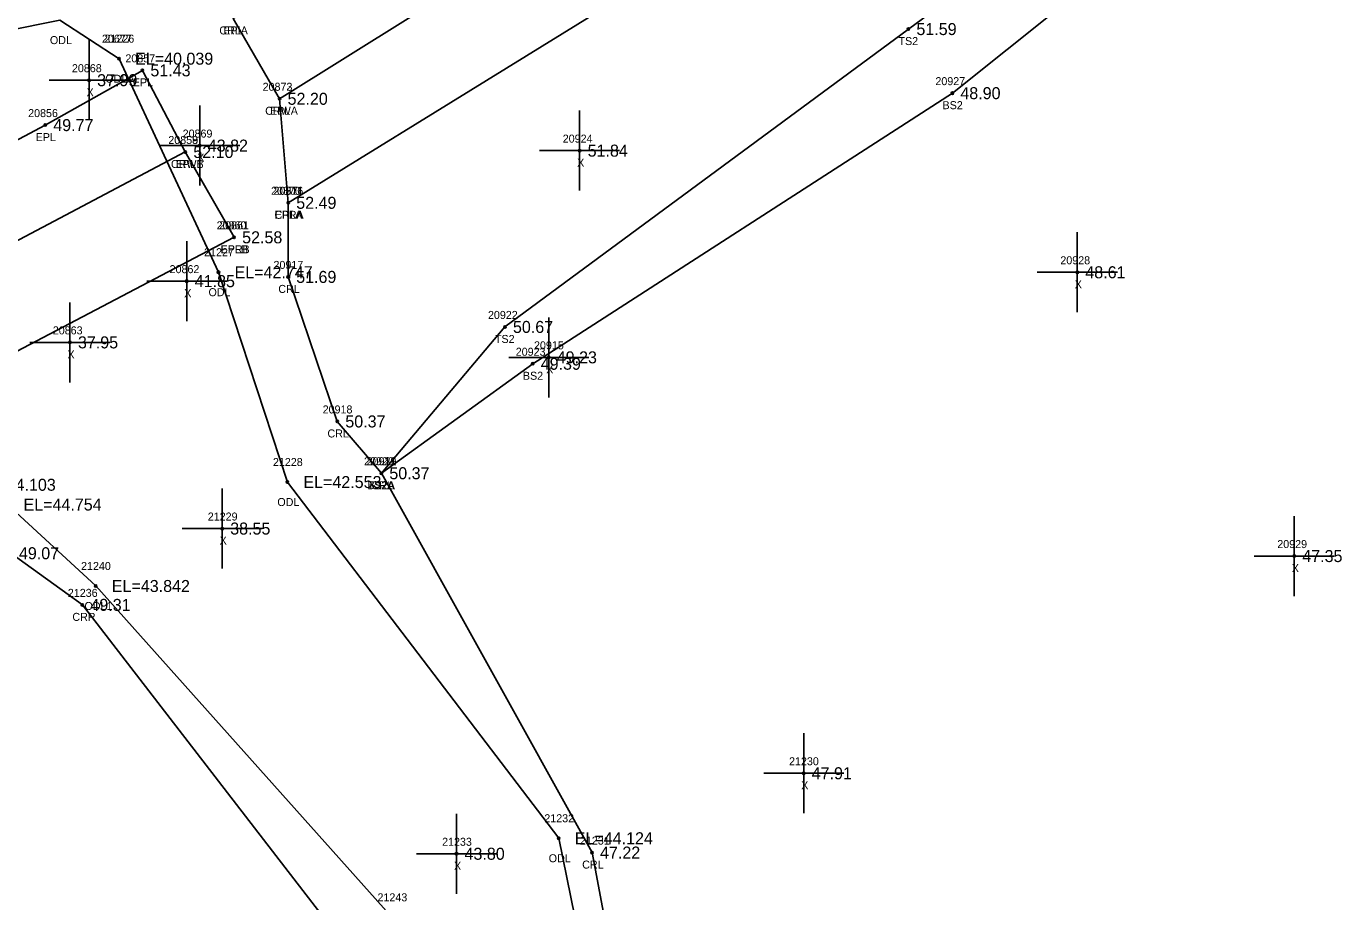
# Model space of a CAD drawing. Extents: x 2420351 to 2422725, y 845330 to 846558.
# Drawn here: x 2421778.1 to 2421942.5, y 845732.5 to 845841.9 of the extents above; entities that cross this region are included whole.
import ezdxf

# ---------------------------------------------------------------- set-up
doc = ezdxf.new("R2010")
doc.units = 0
for name, color, linetype in [('BR_GRID DOTS', 7, 'Continuous'), ('RD_DTM_BkLn1', 7, 'Continuous'), ('RD_DTM_BkLn2', 7, 'Continuous'), ('RD_DTM_BkLn_txCode', 7, 'Continuous'), ('RD_EX_H2O', 7, 'Continuous'), ('RD_EX_H2O_txCode', 7, 'Continuous'), ('RD_EX_Misc', 7, 'Continuous'), ('RD_EX_Misc_txCode', 7, 'Continuous'), ('RD_EX_Road', 7, 'Continuous'), ('RD_EX_Road_txCode', 7, 'Continuous'), ('RD_EX_TX_H2O_ELEV', 7, 'Continuous'), ('RD_EX_TX_Misc_ELEV', 7, 'Continuous'), ('RD_EX_TX_Road_ELEV', 7, 'Continuous'), ('RD_HC_Survey_ELEV', 7, 'Continuous'), ('RD_HC_Survey_txCode', 7, 'Continuous'), ('RD_SMD_Locator', 7, 'Continuous')]:
    doc.layers.add(name, color=color, linetype=linetype)

msp = doc.modelspace()

# ---------------------------------------------------------------- linework, layer by layer
at = {"layer": 'BR_GRID DOTS'}
for p, q in [((2421759.07, 845805.68), (2421797.91, 845826.17)), ((2421764.83, 845794.95), (2421804.01, 845815.51))]:
    msp.add_line(p, q, dxfattribs=at)
msp.add_lwpolyline([(2421764.83, 845794.95), (2421759.07, 845805.68), (2421753.59, 845815.63), (2421766.83, 845822.3), (2421780.42, 845829.53), (2421792.55, 845836.37), (2421797.91, 845826.17), (2421804.01, 845815.51)], dxfattribs=at)
for centre in [(2421792.55, 845836.37), (2421780.42, 845829.53), (2421797.91, 845826.17), (2421797.91, 845826.17), (2421804.01, 845815.51)]:
    msp.add_circle(centre, 0.15, dxfattribs=at)
at = {"layer": 'RD_DTM_BkLn1'}
msp.add_lwpolyline([(2421809.69, 845832.82), (2421858.88, 845863.61), (2421946.63, 845925.83), (2421988.11, 845958.04), (2422060.85, 846015.47), (2422145.87, 846082.37), (2422217.73, 846139.26), (2422291.07, 846197.06), (2422441.76, 846315.63), (2422509.48, 846369.12), (2422585.38, 846428.46), (2422650.19, 846479.15)], dxfattribs=at)
at = {"layer": 'RD_DTM_BkLn2'}
for points in [[(2421822.4, 845786.03), (2421837.84, 845804.31), (2421888.24, 845841.53), (2421930.25, 845872.55), (2421966.04, 845899.72), (2422004.21, 845932.1), (2422041.57, 845964.03)], [(2421822.4, 845786.03), (2421841.31, 845799.71), (2421893.73, 845833.52), (2421934.91, 845866.48), (2422007.56, 845925.47), (2422041.57, 845964.03)]]:
    msp.add_lwpolyline(points, dxfattribs=at)
at = {"layer": 'RD_EX_H2O'}
for points in [[(2421789.64, 845837.83), (2421782.25, 845842.65), (2421762.14, 845838.6), (2421745.54, 845847.69), (2421715.82, 845873.29), (2421690.16, 845897.6), (2421662.52, 845937.52), (2421691.81, 845952.74), (2421695.52, 845998.98), (2421690.3, 846033.46), (2421790.46, 846058.61), (2421873.55, 846071.45), (2421916.6, 846080.01)], [(2421789.64, 845837.83), (2421802.06, 845811.15), (2421810.66, 845784.93), (2421844.56, 845740.42), (2421856.1, 845683.72), (2421854.89, 845664.88), (2421843.25, 845658.16), (2421829.21, 845628.83), (2421830.77, 845610.33), (2421843.38, 845580.1), (2421828.19, 845558.94), (2421831.91, 845499.14), (2421809.98, 845486.71), (2421808.79, 845466.96), (2421839.47, 845434.68), (2421874.6, 845421.86), (2421897.47, 845382.52), (2421913.19, 845366.87)], [(2421810.77, 845819.82), (2421810.76, 845810.56), (2421816.9, 845792.5), (2421822.4, 845786.03), (2421848.72, 845738.63), (2421858.75, 845685.13), (2421860.35, 845662.88), (2421845.9, 845650.47), (2421833.11, 845629.75), (2421840.79, 845614.06), (2421848.44, 845579.41), (2421832.04, 845554.52), (2421837.19, 845498.45), (2421811.62, 845484.13), (2421811.72, 845469.11), (2421841.99, 845438.03), (2421875.97, 845424.56), (2421900.41, 845383.13), (2421915.29, 845367.51)], [(2421769.97, 845784.59), (2421775.7, 845782.12), (2421786.73, 845771.94), (2421823.71, 845730.54), (2421836.28, 845679.34), (2421832.24, 845660.92), (2421820.77, 845638.45), (2421823.1, 845608.96), (2421831.71, 845583.35), (2421823.31, 845575.86), (2421811.92, 845548.94), (2421818.99, 845509.7), (2421790.81, 845485.52), (2421791.34, 845474.13), (2421803.96, 845452.08), (2421836.18, 845421.02), (2421870.76, 845406.66), (2421878.5, 845385.15), (2421867.47, 845378.72), (2421847.36, 845376.11), (2421845.3, 845344.22)], [(2421768.08, 845778.29), (2421776.13, 845776.03), (2421785.06, 845769.58), (2421818.61, 845726.06), (2421831.42, 845677.9), (2421825.05, 845663.86), (2421816.1, 845638.14), (2421820.64, 845608.52), (2421828.09, 845585.14), (2421817.9, 845575.21), (2421808.75, 845549.61), (2421816.7, 845511.81), (2421785.75, 845489.97), (2421789.04, 845473.23), (2421801.09, 845449.66), (2421834.75, 845418.44), (2421870.95, 845402.12), (2421876.24, 845387.07), (2421866.97, 845385.32), (2421844.91, 845376.57), (2421842.84, 845344.63)]]:
    msp.add_lwpolyline(points, dxfattribs=at)
at = {"layer": 'RD_EX_Misc'}
for p, q in [((2421785.9, 845830.14), (2421785.9, 845840.14)), ((2421780.9, 845835.14), (2421790.9, 845835.14)), ((2421799.72, 845821.97), (2421799.72, 845831.97)), ((2421847.17, 845821.34), (2421847.17, 845831.34)), ((2421794.72, 845826.97), (2421804.72, 845826.97)), ((2421842.17, 845826.34), (2421852.17, 845826.34)), ((2421909.34, 845806.14), (2421909.34, 845816.14)), ((2421798.09, 845805.03), (2421798.09, 845815.03)), ((2421904.34, 845811.14), (2421914.34, 845811.14)), ((2421793.09, 845810.03), (2421803.09, 845810.03)), ((2421783.5, 845797.38), (2421783.5, 845807.38)), ((2421843.31, 845795.51), (2421843.31, 845805.51)), ((2421778.5, 845802.38), (2421788.5, 845802.38)), ((2421838.31, 845800.51), (2421848.31, 845800.51)), ((2421802.52, 845774.12), (2421802.52, 845784.12)), ((2421936.44, 845770.68), (2421936.44, 845780.68)), ((2421797.52, 845779.12), (2421807.52, 845779.12)), ((2421931.44, 845775.68), (2421941.44, 845775.68)), ((2421875.16, 845743.54), (2421875.16, 845753.54)), ((2421870.16, 845748.54), (2421880.16, 845748.54)), ((2421831.79, 845733.48), (2421831.79, 845743.48)), ((2421826.79, 845738.48), (2421836.79, 845738.48))]:
    msp.add_line(p, q, dxfattribs=at)
at = {"layer": 'RD_EX_Road'}
for points in [[(2421810.77, 845819.82), (2421809.69, 845832.82), (2421803.88, 845842.86), (2421852.96, 845873.69), (2421939.48, 845935.12), (2421980.78, 845967.01), (2422140.12, 846092.81), (2422210.03, 846148.43), (2422282.88, 846205.21), (2422291.79, 846212.09), (2422354.49, 846261.98), (2422400.82, 846297.88), (2422417.34, 846311.65), (2422435.4, 846324.77), (2422462.49, 846346.77), (2422472.85, 846354.85), (2422502.3, 846378.16), (2422578.05, 846437.54), (2422605.64, 846459.09), (2422626.64, 846476.17), (2422642.61, 846488.86)], [(2421810.77, 845819.82), (2421865.31, 845853.52), (2421953.26, 845916.07), (2421995.06, 845948.03), (2422068.36, 846005.98), (2422153.46, 846073.36), (2422229.55, 846134.03), (2422245.4, 846145.63), (2422297.08, 846186.88), (2422369.77, 846243.69), (2422382.04, 846253.08), (2422449.02, 846305.97), (2422517.14, 846360.1), (2422592.58, 846419.1), (2422657.51, 846470.1)]]:
    msp.add_lwpolyline(points, dxfattribs=at)
at = {"layer": 'RD_SMD_Locator'}
for centre in [(2421888.24, 845841.53), (2421789.64, 845837.83), (2421789.64, 845837.83), (2421785.9, 845835.14), (2421893.73, 845833.52), (2421809.69, 845832.82), (2421809.69, 845832.82), (2421799.72, 845826.97), (2421847.17, 845826.34), (2421810.77, 845819.82), (2421810.77, 845819.82), (2421810.77, 845819.82), (2421804.01, 845815.51), (2421802.06, 845811.15), (2421810.76, 845810.56), (2421909.34, 845811.14), (2421798.09, 845810.03), (2421837.84, 845804.31), (2421783.5, 845802.38), (2421841.31, 845799.71), (2421843.31, 845800.51), (2421816.9, 845792.5), (2421822.4, 845786.03), (2421822.4, 845786.03), (2421822.4, 845786.03), (2421810.66, 845784.93), (2421802.52, 845779.12), (2421936.44, 845775.68), (2421786.73, 845771.94), (2421785.06, 845769.58), (2421875.16, 845748.54), (2421844.56, 845740.42), (2421831.79, 845738.48), (2421848.72, 845738.63)]:
    msp.add_circle(centre, 0.15, dxfattribs=at)

# ---------------------------------------------------------------- texts
at = {"layer": 'RD_DTM_BkLn_txCode'}
for s, p in [('TS2', (2421887, 845839.53)), ('20927', (2421891.61, 845834.52)), ('BS2', (2421892.5, 845831.52)), ('20922', (2421835.72, 845805.31)), ('TS2', (2421836.59, 845802.31)), ('20923', (2421839.19, 845800.71)), ('BS2', (2421840.08, 845797.71)), ('20920', (2421820.24, 845787.03)), ('20921', (2421820.56, 845787.03)), ('TS2A', (2421820.67, 845784.03)), ('BS2A', (2421820.68, 845784.03))]:
    msp.add_text(s, height=1, dxfattribs=at).set_placement(p)
at = {"layer": 'RD_EX_H2O_txCode'}
for s, p in [('CRLA', (2421802.16, 845840.86)), ('ODL', (2421781, 845839.65)), ('20677', (2421787.5, 845839.83)), ('21226', (2421787.82, 845839.83)), ('ODLA', (2421787.91, 845834.83)), ('ODLA', (2421787.91, 845834.83)), ('20916', (2421808.92, 845820.82)), ('CRLA', (2421809.06, 845817.82)), ('21227', (2421800.26, 845813.15)), ('20917', (2421808.93, 845811.56)), ('ODL', (2421800.81, 845808.15)), ('CRL', (2421809.53, 845808.56)), ('20918', (2421815.07, 845793.5)), ('CRL', (2421815.67, 845790.5)), ('21228', (2421808.86, 845786.93)), ('20919', (2421820.56, 845787.03)), ('CRL', (2421821.17, 845784.03)), ('ODL', (2421809.41, 845781.93)), ('21240', (2421784.89, 845773.94)), ('21236', (2421783.24, 845770.58)), ('ODL1', (2421785.32, 845768.94)), ('CRR', (2421783.81, 845767.58)), ('21232', (2421842.76, 845742.42)), ('21231', (2421847.21, 845739.63)), ('ODL', (2421843.31, 845737.42)), ('CRL', (2421847.49, 845736.63)), ('21243', (2421821.92, 845732.54))]:
    msp.add_text(s, height=1, dxfattribs=at).set_placement(p)
at = {"layer": 'RD_EX_Misc_txCode'}
for s, p in [('20868', (2421783.75, 845836.14)), ('X', (2421785.58, 845833.14)), ('20869', (2421797.58, 845827.97)), ('20924', (2421845.06, 845827.34)), ('X', (2421799.4, 845824.97)), ('X', (2421846.86, 845824.34)), ('20928', (2421907.22, 845812.14)), ('20862', (2421795.95, 845811.03)), ('X', (2421797.78, 845808.03)), ('X', (2421909.02, 845809.14)), ('20863', (2421781.36, 845803.38)), ('20915', (2421841.47, 845801.51)), ('X', (2421783.19, 845800.38)), ('X', (2421842.99, 845798.51)), ('21229', (2421800.72, 845780.12)), ('X', (2421802.2, 845777.12)), ('20929', (2421934.32, 845776.68)), ('X', (2421936.13, 845773.68)), ('21230', (2421873.33, 845749.54)), ('X', (2421874.85, 845746.54)), ('21233', (2421829.99, 845739.48)), ('X', (2421831.48, 845736.48))]:
    msp.add_text(s, height=1, dxfattribs=at).set_placement(p)
at = {"layer": 'RD_EX_Road_txCode'}
for s, p in [('EPL', (2421802.67, 845840.86)), ('20857', (2421790.43, 845837.37)), ('EPL', (2421791.35, 845834.37)), ('20872', (2421807.57, 845833.82)), ('20856', (2421778.28, 845830.53)), ('EPL', (2421808.49, 845830.82)), ('EPL', (2421779.22, 845827.53)), ('20858', (2421795.79, 845827.17)), ('EPL', (2421796.71, 845824.17)), ('20870', (2421808.62, 845820.82)), ('20871', (2421808.94, 845820.82)), ('20860', (2421801.83, 845816.51)), ('20861', (2421802.15, 845816.51)), ('EPRA', (2421809.06, 845817.82)), ('EPLA', (2421809.08, 845817.82)), ('EPRB', (2421802.31, 845813.51)), ('EPLB', (2421802.33, 845813.51))]:
    msp.add_text(s, height=1, dxfattribs=at).set_placement(p)
at = {"layer": 'RD_EX_TX_H2O_ELEV'}
for s, p in [('EL=40.039', (2421791.64, 845837.08)), ('EL=40.039', (2421791.64, 845837.08)), ('52.49', (2421811.77, 845819.07)), ('EL=42.747', (2421804.06, 845810.4)), ('51.69', (2421811.76, 845809.81)), ('50.37', (2421817.9, 845791.75)), ('50.37', (2421823.4, 845785.28)), ('EL=44.103', (2421771.97, 845783.84)), ('EL=44.103', (2421771.97, 845783.84)), ('EL=42.553', (2421812.66, 845784.18)), ('EL=44.754', (2421777.7, 845781.37)), ('49.07', (2421777.13, 845775.28)), ('EL=43.842', (2421788.73, 845771.19)), ('49.31', (2421786.06, 845768.83)), ('EL=44.124', (2421846.56, 845739.67)), ('47.22', (2421849.72, 845737.88))]:
    msp.add_text(s, height=1.5, dxfattribs=at).set_placement(p)
at = {"layer": 'RD_EX_TX_Misc_ELEV'}
for s, p in [('51.59', (2421889.24, 845840.78)), ('37.99', (2421786.9, 845834.39)), ('48.90', (2421894.73, 845832.77)), ('43.82', (2421800.72, 845826.22)), ('51.84', (2421848.17, 845825.59)), ('41.85', (2421799.09, 845809.28)), ('48.61', (2421910.34, 845810.39)), ('50.67', (2421838.84, 845803.56)), ('37.95', (2421784.5, 845801.63)), ('49.23', (2421844.31, 845799.76)), ('49.39', (2421842.31, 845798.96)), ('50.37', (2421823.4, 845785.28)), ('50.37', (2421823.4, 845785.28)), ('38.55', (2421803.52, 845778.37)), ('47.35', (2421937.44, 845774.93)), ('47.91', (2421876.16, 845747.79)), ('43.80', (2421832.79, 845737.73))]:
    msp.add_text(s, height=1.5, dxfattribs=at).set_placement(p)
at = {"layer": 'RD_EX_TX_Road_ELEV'}
for s, p in [('51.43', (2421793.55, 845835.62)), ('52.20', (2421810.69, 845832.07)), ('49.77', (2421781.42, 845828.78)), ('52.10', (2421798.91, 845825.42)), ('52.49', (2421811.77, 845819.07)), ('52.49', (2421811.77, 845819.07)), ('52.58', (2421805.01, 845814.76)), ('52.58', (2421805.01, 845814.76))]:
    msp.add_text(s, height=1.5, dxfattribs=at).set_placement(p)
at = {"layer": 'RD_HC_Survey_ELEV'}
for s, p in [('52.20', (2421810.69, 845832.07)), ('52.10', (2421798.91, 845825.42))]:
    msp.add_text(s, height=1.5, dxfattribs=at).set_placement(p)
at = {"layer": 'RD_HC_Survey_txCode'}
for s, p in [('20873', (2421807.57, 845833.82)), ('CRWA', (2421807.89, 845830.82)), ('20859', (2421795.79, 845827.17)), ('CRWB', (2421796.12, 845824.17))]:
    msp.add_text(s, height=1, dxfattribs=at).set_placement(p)

doc.saveas('drawing.dxf')
